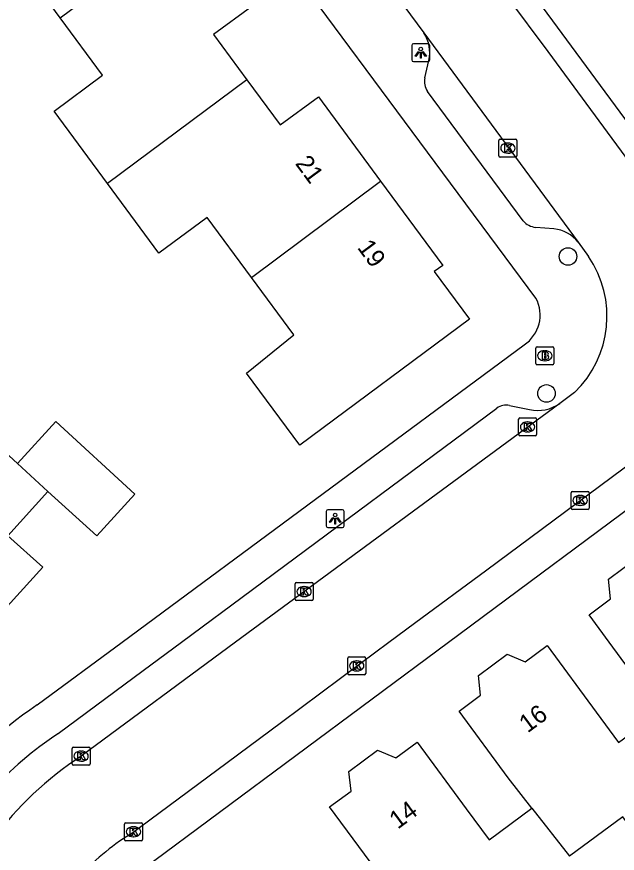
# Model space of a CAD drawing. Extents: x 163427 to 164190, y 380331 to 381641.
# Drawn here: x 163731.44 to 163764.91, y 381238.24 to 381284.84 of the extents above; entities that cross this region are included whole.
import ezdxf

# ---------------------------------------------------------------- set-up
doc = ezdxf.new("R2010")
doc.units = 0
for name, color, linetype in [('IMGEO_Boom', 7, 'Continuous'), ('IMGEO_Brandkraan', 7, 'Continuous'), ('IMGEO_Kolk', 7, 'Continuous'), ('IMGEO_Lichtpunt', 7, 'Continuous'), ('IMGEO_Pand', 7, 'Continuous'), ('IMGEO_Pand_nummerreeks', 7, 'Continuous'), ('IMGEO_Rijbaan_lokaal_open', 7, 'Continuous'), ('IMGEO_Voetpad_open', 7, 'Continuous')]:
    doc.layers.add(name, color=color, linetype=linetype)

msp = doc.modelspace()

# ---------------------------------------------------------------- linework, layer by layer
at = {"layer": 'IMGEO_Boom'}
for centre in [(163762.159, 381271.482), (163760.965, 381263.853)]:
    msp.add_circle(centre, 0.489, dxfattribs=at)
at = {"layer": 'IMGEO_Brandkraan'}
for p, q in [((163760.37, 381265.529), (163760.37, 381266.381)), ((163760.445, 381266.455), (163761.297, 381266.455)), ((163760.858, 381266.235), (163760.883, 381266.235)), ((163761.371, 381266.381), (163761.371, 381265.529)), ((163761.297, 381265.455), (163760.445, 381265.455)), ((163760.881, 381265.675), (163760.856, 381265.675))]:
    msp.add_line(p, q, dxfattribs=at)
for points in [[(163760.37, 381265.529), (163760.37, 381266.381)], [(163760.445, 381266.455), (163761.297, 381266.455)], [(163761.371, 381266.381), (163761.371, 381265.529)], [(163760.718, 381266.155), (163760.718, 381265.755), (163760.931, 381265.755)], [(163760.949, 381266.155), (163760.718, 381266.155)], [(163760.897, 381266.074), (163760.843, 381266.074), (163760.843, 381265.998)], [(163760.843, 381265.998), (163760.896, 381265.998)], [(163760.905, 381265.922), (163760.843, 381265.922), (163760.843, 381265.841)], [(163760.843, 381265.841), (163760.905, 381265.841)], [(163761.297, 381265.455), (163760.445, 381265.455)]]:
    msp.add_lwpolyline(points, dxfattribs=at)
for centre, radius, start, end in [((163760.447, 381266.379), 0.0765, 91.552, 178.448), ((163760.447, 381266.379), 0.0765, 91.552, 178.448), ((163761.295, 381266.379), 0.0765, 1.552, 88.448), ((163761.295, 381266.379), 0.0765, 1.552, 88.448), ((163760.898, 381266.036), 0.0379, 267.8285, 90.9355), ((163760.906, 381265.881), 0.0404, 269.8759, 90.5077), ((163760.937, 381266.006), 0.251, 268.6676, 293.5347), ((163760.953, 381266.01), 0.145, 59.4692, 91.5367), ((163760.978, 381266.057), 0.0922, 285.5137, 58.1501), ((163760.983, 381265.865), 0.105, 301.3115, 78.989), ((163760.447, 381265.531), 0.0765, 181.552, 268.448), ((163760.447, 381265.531), 0.0765, 181.552, 268.448), ((163761.295, 381265.531), 0.0765, 271.552, 358.448), ((163761.295, 381265.531), 0.0765, 271.552, 358.448)]:
    msp.add_arc(centre, radius, start, end, dxfattribs=at)
for centre, major_axis, ratio, start_param, end_param in [((163760.857, 381265.955), (-0.387, 0.002), 0.722429, 4.712389, 7.853982), ((163760.882, 381265.955), (-0.39, 0.002), 0.717154, 1.570796, 4.712389)]:
    msp.add_ellipse(centre, major_axis=major_axis, ratio=ratio, start_param=start_param, end_param=end_param, dxfattribs=at)
at = {"layer": 'IMGEO_Kolk'}
for p, q in [((163758.311, 381277.089), (163758.311, 381277.941)), ((163758.386, 381278.015), (163759.238, 381278.015)), ((163759.312, 381277.941), (163759.312, 381277.089)), ((163758.799, 381277.795), (163758.824, 381277.795)), ((163759.238, 381277.015), (163758.386, 381277.015)), ((163758.822, 381277.235), (163758.797, 381277.235)), ((163759.408, 381261.563), (163759.408, 381262.415)), ((163759.483, 381262.489), (163760.335, 381262.489)), ((163759.896, 381262.269), (163759.921, 381262.269)), ((163760.409, 381262.415), (163760.409, 381261.563)), ((163759.919, 381261.709), (163759.894, 381261.709)), ((163760.335, 381261.489), (163759.483, 381261.489)), ((163762.339, 381257.47), (163762.339, 381258.322)), ((163762.414, 381258.396), (163763.266, 381258.396)), ((163763.34, 381258.322), (163763.34, 381257.47)), ((163762.827, 381258.176), (163762.852, 381258.176)), ((163763.266, 381257.396), (163762.414, 381257.396)), ((163762.85, 381257.616), (163762.825, 381257.616)), ((163746.952, 381252.392), (163746.952, 381253.244)), ((163747.027, 381253.318), (163747.879, 381253.318)), ((163747.953, 381253.244), (163747.953, 381252.392)), ((163747.44, 381253.098), (163747.465, 381253.098)), ((163747.879, 381252.318), (163747.027, 381252.318)), ((163747.463, 381252.538), (163747.438, 381252.538)), ((163749.886, 381248.251), (163749.886, 381249.103)), ((163749.961, 381249.177), (163750.813, 381249.177)), ((163750.887, 381249.103), (163750.887, 381248.251)), ((163750.374, 381248.957), (163750.399, 381248.957)), ((163750.813, 381248.177), (163749.961, 381248.177)), ((163750.397, 381248.397), (163750.372, 381248.397)), ((163734.525, 381243.223), (163734.525, 381244.075)), ((163734.6, 381244.149), (163735.452, 381244.149)), ((163735.013, 381243.929), (163735.038, 381243.929)), ((163735.526, 381244.075), (163735.526, 381243.223)), ((163735.452, 381243.149), (163734.6, 381243.149)), ((163735.036, 381243.369), (163735.011, 381243.369)), ((163737.443, 381239.011), (163737.443, 381239.863)), ((163737.518, 381239.937), (163738.37, 381239.937)), ((163737.931, 381239.717), (163737.956, 381239.717)), ((163738.444, 381239.863), (163738.444, 381239.011)), ((163738.37, 381238.937), (163737.518, 381238.937)), ((163737.954, 381239.157), (163737.929, 381239.157))]:
    msp.add_line(p, q, dxfattribs=at)
for points in [[(163758.311, 381277.089), (163758.311, 381277.941)], [(163758.386, 381278.015), (163759.238, 381278.015)], [(163759.312, 381277.941), (163759.312, 381277.089)], [(163758.632, 381277.715), (163758.755, 381277.715), (163758.755, 381277.564), (163758.885, 381277.715), (163759.049, 381277.715), (163758.903, 381277.564), (163759.056, 381277.315), (163758.904, 381277.315), (163758.819, 381277.479), (163758.755, 381277.412), (163758.755, 381277.315), (163758.632, 381277.315), (163758.632, 381277.715)], [(163759.238, 381277.015), (163758.386, 381277.015)], [(163759.408, 381261.563), (163759.408, 381262.415)], [(163759.483, 381262.489), (163760.335, 381262.489)], [(163759.729, 381262.189), (163759.852, 381262.189), (163759.852, 381262.038), (163759.982, 381262.189), (163760.146, 381262.189), (163760, 381262.038), (163760.153, 381261.789), (163760.001, 381261.789), (163759.916, 381261.953), (163759.852, 381261.886), (163759.852, 381261.789), (163759.729, 381261.789), (163759.729, 381262.189)], [(163760.409, 381262.415), (163760.409, 381261.563)], [(163760.335, 381261.489), (163759.483, 381261.489)], [(163762.339, 381257.47), (163762.339, 381258.322)], [(163762.414, 381258.396), (163763.266, 381258.396)], [(163763.34, 381258.322), (163763.34, 381257.47)], [(163762.66, 381258.096), (163762.783, 381258.096), (163762.783, 381257.945), (163762.913, 381258.096), (163763.077, 381258.096), (163762.931, 381257.945), (163763.084, 381257.696), (163762.932, 381257.696), (163762.847, 381257.86), (163762.783, 381257.793), (163762.783, 381257.696), (163762.66, 381257.696), (163762.66, 381258.096)], [(163763.266, 381257.396), (163762.414, 381257.396)], [(163746.952, 381252.392), (163746.952, 381253.244)], [(163747.027, 381253.318), (163747.879, 381253.318)], [(163747.953, 381253.244), (163747.953, 381252.392)], [(163747.273, 381253.018), (163747.396, 381253.018), (163747.396, 381252.867), (163747.526, 381253.018), (163747.69, 381253.018), (163747.544, 381252.867), (163747.697, 381252.618), (163747.545, 381252.618), (163747.46, 381252.782), (163747.396, 381252.715), (163747.396, 381252.618), (163747.273, 381252.618), (163747.273, 381253.018)], [(163747.879, 381252.318), (163747.027, 381252.318)], [(163749.886, 381248.251), (163749.886, 381249.103)], [(163749.961, 381249.177), (163750.813, 381249.177)], [(163750.887, 381249.103), (163750.887, 381248.251)], [(163750.207, 381248.877), (163750.33, 381248.877), (163750.33, 381248.726), (163750.46, 381248.877), (163750.624, 381248.877), (163750.478, 381248.726), (163750.631, 381248.477), (163750.479, 381248.477), (163750.394, 381248.641), (163750.33, 381248.574), (163750.33, 381248.477), (163750.207, 381248.477), (163750.207, 381248.877)], [(163750.813, 381248.177), (163749.961, 381248.177)], [(163734.525, 381243.223), (163734.525, 381244.075)], [(163734.6, 381244.149), (163735.452, 381244.149)], [(163735.526, 381244.075), (163735.526, 381243.223)], [(163734.846, 381243.849), (163734.969, 381243.849), (163734.969, 381243.698), (163735.099, 381243.849), (163735.263, 381243.849), (163735.117, 381243.698), (163735.27, 381243.449), (163735.118, 381243.449), (163735.033, 381243.613), (163734.969, 381243.546), (163734.969, 381243.449), (163734.846, 381243.449), (163734.846, 381243.849)], [(163735.452, 381243.149), (163734.6, 381243.149)], [(163737.443, 381239.011), (163737.443, 381239.863)], [(163737.518, 381239.937), (163738.37, 381239.937)], [(163738.444, 381239.863), (163738.444, 381239.011)], [(163737.764, 381239.637), (163737.887, 381239.637), (163737.887, 381239.486), (163738.017, 381239.637), (163738.181, 381239.637), (163738.035, 381239.486), (163738.188, 381239.237), (163738.036, 381239.237), (163737.951, 381239.401), (163737.887, 381239.334), (163737.887, 381239.237), (163737.764, 381239.237), (163737.764, 381239.637)], [(163738.37, 381238.937), (163737.518, 381238.937)]]:
    msp.add_lwpolyline(points, dxfattribs=at)
for centre, start, end in [((163758.388, 381277.939), 91.552, 178.448), ((163758.388, 381277.939), 91.552, 178.448), ((163759.236, 381277.939), 1.552, 88.448), ((163759.236, 381277.939), 1.552, 88.448), ((163758.388, 381277.091), 181.552, 268.448), ((163758.388, 381277.091), 181.552, 268.448), ((163759.236, 381277.091), 271.552, 358.448), ((163759.236, 381277.091), 271.552, 358.448), ((163759.485, 381262.413), 91.552, 178.448), ((163759.485, 381262.413), 91.552, 178.448), ((163760.333, 381262.413), 1.552, 88.448), ((163760.333, 381262.413), 1.552, 88.448), ((163759.485, 381261.565), 181.552, 268.448), ((163759.485, 381261.565), 181.552, 268.448), ((163760.333, 381261.565), 271.552, 358.448), ((163760.333, 381261.565), 271.552, 358.448), ((163762.416, 381258.32), 91.552, 178.448), ((163762.416, 381258.32), 91.552, 178.448), ((163763.264, 381258.32), 1.552, 88.448), ((163763.264, 381258.32), 1.552, 88.448), ((163762.416, 381257.472), 181.552, 268.448), ((163762.416, 381257.472), 181.552, 268.448), ((163763.264, 381257.472), 271.552, 358.448), ((163763.264, 381257.472), 271.552, 358.448), ((163747.029, 381253.242), 91.552, 178.448), ((163747.029, 381253.242), 91.552, 178.448), ((163747.877, 381253.242), 1.552, 88.448), ((163747.877, 381253.242), 1.552, 88.448), ((163747.029, 381252.394), 181.552, 268.448), ((163747.029, 381252.394), 181.552, 268.448), ((163747.877, 381252.394), 271.552, 358.448), ((163747.877, 381252.394), 271.552, 358.448), ((163749.963, 381249.101), 91.552, 178.448), ((163749.963, 381249.101), 91.552, 178.448), ((163750.811, 381249.101), 1.552, 88.448), ((163750.811, 381249.101), 1.552, 88.448), ((163749.963, 381248.253), 181.552, 268.448), ((163749.963, 381248.253), 181.552, 268.448), ((163750.811, 381248.253), 271.552, 358.448), ((163750.811, 381248.253), 271.552, 358.448), ((163734.602, 381244.073), 91.552, 178.448), ((163734.602, 381244.073), 91.552, 178.448), ((163735.45, 381244.073), 1.552, 88.448), ((163735.45, 381244.073), 1.552, 88.448), ((163734.602, 381243.225), 181.552, 268.448), ((163734.602, 381243.225), 181.552, 268.448), ((163735.45, 381243.225), 271.552, 358.448), ((163735.45, 381243.225), 271.552, 358.448), ((163737.52, 381239.861), 91.552, 178.448), ((163737.52, 381239.861), 91.552, 178.448), ((163738.368, 381239.861), 1.552, 88.448), ((163738.368, 381239.861), 1.552, 88.448), ((163737.52, 381239.013), 181.552, 268.448), ((163737.52, 381239.013), 181.552, 268.448), ((163738.368, 381239.013), 271.552, 358.448), ((163738.368, 381239.013), 271.552, 358.448)]:
    msp.add_arc(centre, 0.0765, start, end, dxfattribs=at)
for centre, major_axis, ratio, start_param, end_param in [((163758.798, 381277.515), (-0.387, 0.002), 0.722429, 4.712389, 7.853982), ((163758.823, 381277.515), (-0.39, 0.002), 0.717154, 1.570796, 4.712389), ((163759.895, 381261.989), (-0.387, 0.002), 0.722429, 4.712389, 7.853982), ((163759.92, 381261.989), (-0.39, 0.002), 0.717154, 1.570796, 4.712389), ((163762.826, 381257.896), (-0.387, 0.002), 0.722429, 4.712389, 7.853982), ((163762.851, 381257.896), (-0.39, 0.002), 0.717154, 1.570796, 4.712389), ((163747.439, 381252.818), (-0.387, 0.002), 0.722429, 4.712389, 7.853982), ((163747.464, 381252.818), (-0.39, 0.002), 0.717154, 1.570796, 4.712389), ((163750.373, 381248.677), (-0.387, 0.002), 0.722429, 4.712389, 7.853982), ((163750.398, 381248.677), (-0.39, 0.002), 0.717154, 1.570796, 4.712389), ((163735.012, 381243.649), (-0.387, 0.002), 0.722429, 4.712389, 7.853982), ((163735.037, 381243.649), (-0.39, 0.002), 0.717154, 1.570796, 4.712389), ((163737.93, 381239.437), (-0.387, 0.002), 0.722429, 4.712389, 7.853982), ((163737.955, 381239.437), (-0.39, 0.002), 0.717154, 1.570796, 4.712389)]:
    msp.add_ellipse(centre, major_axis=major_axis, ratio=ratio, start_param=start_param, end_param=end_param, dxfattribs=at)
at = {"layer": 'IMGEO_Lichtpunt'}
for p, q in [((163753.456, 381283.24), (163753.456, 381282.433)), ((163753.456, 381283.24), (163753.456, 381282.433)), ((163754.358, 381283.335), (163753.55, 381283.335)), ((163754.358, 381283.335), (163753.55, 381283.335)), ((163754.452, 381282.433), (163754.452, 381283.24)), ((163754.452, 381282.433), (163754.452, 381283.24)), ((163753.55, 381282.339), (163754.358, 381282.339)), ((163753.55, 381282.339), (163754.358, 381282.339)), ((163749.586, 381257.377), (163748.778, 381257.377)), ((163749.586, 381257.377), (163748.778, 381257.377)), ((163748.684, 381257.282), (163748.684, 381256.475)), ((163748.684, 381257.282), (163748.684, 381256.475)), ((163749.68, 381256.475), (163749.68, 381257.282)), ((163749.68, 381256.475), (163749.68, 381257.282)), ((163748.778, 381256.381), (163749.586, 381256.381)), ((163748.778, 381256.381), (163749.586, 381256.381))]:
    msp.add_line(p, q, dxfattribs=at)
for points in [[(163753.83, 381282.904), (163753.869, 381282.876), (163753.681, 381282.614), (163753.643, 381282.641), (163753.83, 381282.904)], [(163753.932, 381282.856), (163753.979, 381282.856), (163753.979, 381282.534), (163753.932, 381282.534), (163753.932, 381282.856)], [(163754.042, 381282.876), (163754.08, 381282.903), (163754.267, 381282.641), (163754.228, 381282.613), (163754.042, 381282.876)], [(163749.058, 381256.946), (163749.097, 381256.918), (163748.909, 381256.656), (163748.871, 381256.683), (163749.058, 381256.946)], [(163749.27, 381256.918), (163749.308, 381256.945), (163749.495, 381256.683), (163749.456, 381256.655), (163749.27, 381256.918)], [(163749.16, 381256.898), (163749.207, 381256.898), (163749.207, 381256.576), (163749.16, 381256.576), (163749.16, 381256.898)]]:
    msp.add_lwpolyline(points, dxfattribs=at)
for centre in [(163753.955, 381283.038), (163749.183, 381257.08)]:
    msp.add_circle(centre, 0.0994, dxfattribs=at)
for centre, start, end in [((163753.55, 381283.24), 90, 180), ((163753.55, 381283.24), 90, 180), ((163754.358, 381283.24), 0, 90), ((163754.358, 381283.24), 0, 90), ((163753.55, 381282.433), 180, 270), ((163753.55, 381282.433), 180, 270), ((163754.358, 381282.433), 270, 0), ((163754.358, 381282.433), 270, 360), ((163748.778, 381257.282), 90, 180), ((163748.778, 381257.282), 90, 180), ((163749.586, 381257.282), 0, 90), ((163749.586, 381257.282), 0, 90), ((163748.778, 381256.475), 180, 270), ((163748.778, 381256.475), 180, 270), ((163749.586, 381256.475), 270, 0), ((163749.586, 381256.475), 270, 360)]:
    msp.add_arc(centre, 0.0946, start, end, dxfattribs=at)
at = {"layer": 'IMGEO_Pand'}
for points in [[(163733.86, 381284.779), (163731.397, 381288.12), (163728.694, 381286.127), (163725.672, 381290.228), (163729.431, 381292.999), (163733.455, 381295.966), (163735.432, 381293.292), (163737.561, 381294.848), (163741.052, 381290.128)], [(163733.86, 381284.779), (163741.052, 381290.128)], [(163741.052, 381290.128), (163744.543, 381285.407), (163742.412, 381283.838), (163744.264, 381281.324)], [(163736.491, 381275.546), (163733.519, 381279.579), (163736.223, 381281.573), (163733.86, 381284.779)], [(163744.264, 381281.324), (163736.491, 381275.546)], [(163744.264, 381281.324), (163746.118, 381278.808), (163748.25, 381280.379), (163751.72, 381275.682)], [(163744.524, 381270.307), (163742.059, 381273.651), (163739.356, 381271.658), (163736.491, 381275.546)], [(163751.72, 381275.682), (163755.192, 381270.983), (163754.701, 381270.639), (163756.667, 381267.981), (163747.223, 381260.972), (163744.249, 381264.991), (163746.879, 381267.112), (163744.524, 381270.307)], [(163744.524, 381270.307), (163751.72, 381275.682)], [(163722.304, 381255.905), (163725.064, 381258.916), (163722.595, 381261.18), (163726.044, 381264.942), (163731.481, 381259.957)], [(163731.481, 381259.957), (163733.616, 381262.286), (163738.025, 381258.243), (163735.904, 381255.921), (163733.162, 381258.388)], [(163733.162, 381258.388), (163731.481, 381259.957)], [(163733.162, 381258.388), (163730.943, 381255.926), (163732.887, 381254.174), (163729.076, 381250), (163728.92, 381249.83)], [(163767.358, 381246.156), (163766.061, 381247.821), (163764.456, 381250), (163763.334, 381251.523), (163764.531, 381252.412), (163764.416, 381253.509), (163766.011, 381254.689), (163767.021, 381254.26), (163768.228, 381255.156), (163771.01, 381251.413), (163772.265, 381249.725), (163774.663, 381251.508)], [(163760.154, 381240.746), (163758.827, 381242.444), (163756.091, 381246.159), (163757.288, 381247.048), (163757.173, 381248.145), (163758.768, 381249.325), (163759.778, 381248.896), (163761, 381249.804), (163763.727, 381246.102), (163764.979, 381244.403), (163767.358, 381246.156)], [(163754.397, 381233.352), (163748.871, 381240.82), (163750.07, 381241.705), (163749.955, 381242.803), (163751.55, 381243.983), (163752.57, 381243.55), (163753.76, 381244.43), (163756.49, 381240.723), (163757.767, 381238.988), (163760.154, 381240.746)], [(163769.489, 381243.418), (163772.454, 381239.395), (163768.43, 381236.429), (163768.183, 381236.247), (163765.218, 381240.269), (163762.241, 381238.075)], [(163760.154, 381240.746), (163762.241, 381238.075)]]:
    msp.add_lwpolyline(points, dxfattribs=at)
at = {"layer": 'IMGEO_Rijbaan_lokaal_open'}
for points in [[(163748.164, 381292.114), (163748.432, 381291.653), (163749.62, 381290.048), (163754.126, 381283.93)], [(163768.931, 381272.214), (163766.855, 381275.036), (163764.63, 381278.054), (163761.048, 381282.907), (163758.816, 381285.926), (163755.171, 381290.857)], [(163754.126, 381283.93), (163762.737, 381272.275)], [(163762.737, 381272.275), (163763.306, 381271.485)], [(163762.532, 381263.908), (163761.7, 381263.296)], [(163761.7, 381263.296), (163743.625, 381250), (163735.024, 381243.646)], [(163737.769, 381239.302), (163743.166, 381243.303), (163746.197, 381245.539), (163750.571, 381248.802), (163752.181, 381250), (163753.605, 381251.059), (163757.64, 381254.032), (163760.666, 381256.281), (163764.646, 381259.224), (163767.663, 381261.473)]]:
    msp.add_lwpolyline(points, dxfattribs=at)
for centre, radius, start, end in [((163758.422, 381268.156), 5.911, 314.0574, 34.2774), ((163745.466, 381227.654), 19.099, 123.1417, 163.7666), ((163744.266, 381228.689), 12.444, 121.472, 139.199)]:
    msp.add_arc(centre, radius, start, end, dxfattribs=at)
at = {"layer": 'IMGEO_Voetpad_open'}
for points in [[(163760.371, 381269.157), (163740.553, 381295.871), (163741.259, 381296.424), (163738.778, 381299.792)], [(163774.583, 381264.129), (163775.788, 381264.982), (163769.92, 381272.943), (163755.631, 381292.33)], [(163754.174, 381281.433), (163754.408, 381282.4)], [(163759.666, 381273.463), (163754.327, 381280.672)], [(163761.369, 381273.018), (163760.36, 381273.101)], [(163732.571, 381246.499), (163737.308, 381250), (163759.71, 381266.555)], [(163733.756, 381244.918), (163738.481, 381248.419), (163740.615, 381250), (163744.576, 381252.935), (163758.197, 381263.027)], [(163758.907, 381263.183), (163760.014, 381262.95)], [(163738.486, 381237.379), (163755.493, 381250), (163767.711, 381259.062)]]:
    msp.add_lwpolyline(points, dxfattribs=at)
for centre, radius, start, end in [((163752.458, 381282.832), 1.998, 347.5243, 33.362), ((163755.199, 381281.243), 1.043, 169.5174, 213.2183), ((163760.495, 381274.205), 1.112, 221.8541, 263.0516), ((163761.181, 381271.041), 1.986, 38.4221, 84.5626), ((163758.627, 381268.215), 1.982, 303.125, 28.3677), ((163758.726, 381262.315), 0.887, 78.205, 126.579), ((163760.461, 381265.054), 2.151, 258.0148, 305.1796), ((163745.109, 381227.856), 22.467, 123.9213, 164.2166), ((163744.965, 381228.013), 20.283, 123.5458, 137.7188)]:
    msp.add_arc(centre, radius, start, end, dxfattribs=at)

# ---------------------------------------------------------------- texts
at = {"layer": 'IMGEO_Pand_nummerreeks'}
for s, rotation, p in [('21', 306.4579, (163746.924, 381276.655)), ('19', 306.4579, (163750.382, 381271.975)), ('16', 36.5948, (163759.91, 381244.909)), ('14', 36.4401, (163752.672, 381239.55))]:
    msp.add_text(s, height=1, rotation=rotation, dxfattribs=at).set_placement(p)

doc.saveas('drawing.dxf')
